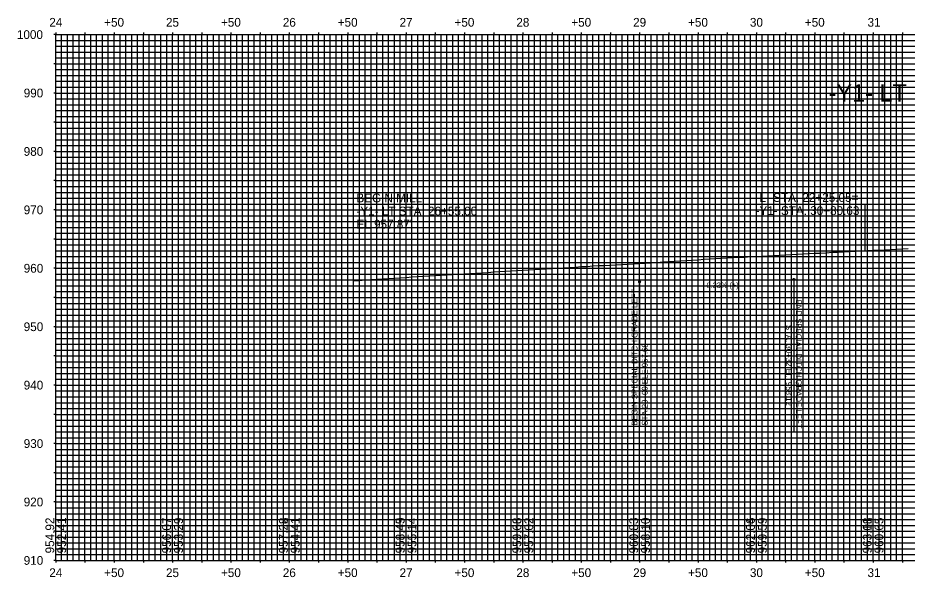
# Model space of a CAD drawing. Extents: x 1367 to 2832, y 896 to 1374.
# Drawn here: x 1367 to 2129, y 896 to 1374 of the extents above; entities that cross this region are included whole.
import ezdxf

# ---------------------------------------------------------------- set-up
doc = ezdxf.new("R2010")
doc.units = 0
for name, color, linetype in [('E_NCDOT_Terrain_Model_Contour_Major', 7, 'Continuous'), ('E_NCDOT_Vertical_Profile_Strip_Grade', 7, 'Continuous'), ('P_NCDOT_Horizontal_Alignment_Curve_and_Spiral_Data', 7, 'Continuous'), ('P_NCDOT_Horizontal_Alignment_Direction_Label', 7, 'Continuous'), ('P_NCDOT_Horizontal_Alignment_Station_Label', 7, 'Continuous'), ('P_NCDOT_Horizontal_Alignment_Station_Major_Label', 7, 'Continuous'), ('P_NCDOT_Horizontal_Alignment_Tick_Large', 7, 'Continuous'), ('P_NCDOT_Horizontal_Alignment_Tick_Small', 7, 'Continuous'), ('P_NCDOT_Vertical_Profile_Ditch_Grade_Left_Label', 7, 'Continuous'), ('P_NCDOT_Vertical_Profile_Ditch_Grade_Right', 7, 'Continuous'), ('P_NCDOT_Vertical_Profile_Strip_Grade', 7, 'Continuous'), ('P_RDY_Profile_Special_Ditch_L', 7, 'Continuous')]:
    doc.layers.add(name, color=color, linetype=linetype)

msp = doc.modelspace()

# ---------------------------------------------------------------- linework, layer by layer
at = {"layer": 'E_NCDOT_Terrain_Model_Contour_Major'}
msp.add_lwpolyline([(1655, 1149.35), (1660, 1149.68), (1665, 1150.01), (1670, 1150.35), (1675, 1150.68), (1680, 1151.01), (1685, 1151.32), (1690, 1151.61), (1695, 1151.94), (1700, 1152.23), (1705, 1152.56), (1710, 1152.88), (1715, 1153.19), (1720, 1153.46), (1725, 1153.76), (1730, 1154.05), (1735, 1154.35), (1740, 1154.67), (1745, 1154.97), (1750, 1155.27), (1755, 1155.59), (1760, 1155.91), (1765, 1156.22), (1770, 1156.51), (1775, 1156.83), (1780, 1157.13), (1785, 1157.44), (1790, 1157.76), (1795, 1158.07), (1800, 1158.38), (1805, 1158.69), (1810, 1159), (1815, 1159.32), (1820, 1159.61), (1825, 1159.91), (1830, 1160.22), (1835, 1160.49), (1840, 1160.79), (1845, 1161.09), (1850, 1161.39), (1855, 1161.67), (1860, 1161.98), (1865, 1162.25), (1870, 1162.53), (1875, 1162.81), (1880, 1163.07), (1885, 1163.34), (1890, 1163.56), (1895, 1163.85), (1900, 1164.14), (1905, 1164.46), (1910, 1164.77), (1915, 1165.09), (1920, 1165.44), (1925, 1165.75), (1930, 1166.06), (1935, 1166.37), (1940, 1166.68), (1945, 1167.01), (1950, 1167.34), (1955, 1167.67), (1960, 1167.99), (1965, 1168.32), (1970, 1168.64), (1975, 1168.91), (1980, 1169.16), (1985, 1169.41), (1990, 1169.66), (1995, 1169.96), (2000, 1170.22), (2005, 1170.5), (2010, 1170.77), (2015, 1171.06), (2020, 1171.32), (2025, 1171.59), (2030, 1171.87), (2035, 1172.1), (2040, 1172.36), (2045, 1172.59), (2050, 1172.83), (2055, 1173.08), (2060, 1173.36), (2065, 1173.66), (2070, 1173.88), (2075, 1174.15), (2080, 1174.41), (2085, 1174.68), (2090, 1174.94), (2095, 1175.17), (2100, 1175.4), (2105, 1175.63), (2110, 1175.86), (2115, 1176.11), (2120, 1176.36), (2125, 1176.6), (2130, 1176.87)], dxfattribs=at)
at = {"layer": 'P_NCDOT_Horizontal_Alignment_Station_Label'}
for p, q in [((1450, 910), (1450, 1360)), ((1500, 910), (1500, 1360)), ((1550, 910), (1550, 1360)), ((1600, 910), (1600, 1360)), ((1650, 910), (1650, 1360)), ((1700, 910), (1700, 1360)), ((1750, 910), (1750, 1360)), ((1800, 910), (1800, 1360)), ((1850, 910), (1850, 1360)), ((1900, 910), (1900, 1360)), ((1950, 910), (1950, 1360)), ((2000, 910), (2000, 1360)), ((2050, 910), (2050, 1360)), ((2100, 910), (2100, 1360)), ((1400, 1310), (2800, 1310)), ((1400, 1260), (2800, 1260)), ((1400, 1210), (2800, 1210)), ((1400, 1160), (2800, 1160)), ((1400, 1110), (2800, 1110)), ((1400, 1060), (2800, 1060)), ((1400, 1010), (2800, 1010)), ((1400, 960), (2800, 960))]:
    msp.add_line(p, q, dxfattribs=at)
at = {"layer": 'P_NCDOT_Horizontal_Alignment_Station_Major_Label'}
for p, q in [((1405, 910), (1405, 1360)), ((1410, 910), (1410, 1360)), ((1415, 910), (1415, 1360)), ((1420, 910), (1420, 1360)), ((1430, 910), (1430, 1360)), ((1435, 910), (1435, 1360)), ((1440, 910), (1440, 1360)), ((1445, 910), (1445, 1360)), ((1455, 910), (1455, 1360)), ((1460, 910), (1460, 1360)), ((1465, 910), (1465, 1360)), ((1470, 910), (1470, 1360)), ((1480, 910), (1480, 1360)), ((1485, 910), (1485, 1360)), ((1490, 910), (1490, 1360)), ((1495, 910), (1495, 1360)), ((1505, 910), (1505, 1360)), ((1510, 910), (1510, 1360)), ((1515, 910), (1515, 1360)), ((1520, 910), (1520, 1360)), ((1530, 910), (1530, 1360)), ((1535, 910), (1535, 1360)), ((1540, 910), (1540, 1360)), ((1545, 910), (1545, 1360)), ((1555, 910), (1555, 1360)), ((1560, 910), (1560, 1360)), ((1565, 910), (1565, 1360)), ((1570, 910), (1570, 1360)), ((1580, 910), (1580, 1360)), ((1585, 910), (1585, 1360)), ((1590, 910), (1590, 1360)), ((1595, 910), (1595, 1360)), ((1605, 910), (1605, 1360)), ((1610, 910), (1610, 1360)), ((1615, 910), (1615, 1360)), ((1620, 910), (1620, 1360)), ((1630, 910), (1630, 1360)), ((1635, 910), (1635, 1360)), ((1640, 910), (1640, 1360)), ((1645, 910), (1645, 1360)), ((1655, 910), (1655, 1360)), ((1660, 910), (1660, 1360)), ((1665, 910), (1665, 1360)), ((1670, 910), (1670, 1360)), ((1680, 910), (1680, 1360)), ((1685, 910), (1685, 1360)), ((1690, 910), (1690, 1360)), ((1695, 910), (1695, 1360)), ((1705, 910), (1705, 1360)), ((1710, 910), (1710, 1360)), ((1715, 910), (1715, 1360)), ((1720, 910), (1720, 1360)), ((1730, 910), (1730, 1360)), ((1735, 910), (1735, 1360)), ((1740, 910), (1740, 1360)), ((1745, 910), (1745, 1360)), ((1755, 910), (1755, 1360)), ((1760, 910), (1760, 1360)), ((1765, 910), (1765, 1360)), ((1770, 910), (1770, 1360)), ((1780, 910), (1780, 1360)), ((1785, 910), (1785, 1360)), ((1790, 910), (1790, 1360)), ((1795, 910), (1795, 1360)), ((1805, 910), (1805, 1360)), ((1810, 910), (1810, 1360)), ((1815, 910), (1815, 1360)), ((1820, 910), (1820, 1360)), ((1830, 910), (1830, 1360)), ((1835, 910), (1835, 1360)), ((1840, 910), (1840, 1360)), ((1845, 910), (1845, 1360)), ((1855, 910), (1855, 1360)), ((1860, 910), (1860, 1360)), ((1865, 910), (1865, 1360)), ((1870, 910), (1870, 1360)), ((1880, 910), (1880, 1360)), ((1885, 910), (1885, 1360)), ((1890, 910), (1890, 1360)), ((1895, 910), (1895, 1360)), ((1905, 910), (1905, 1360)), ((1910, 910), (1910, 1360)), ((1915, 910), (1915, 1360)), ((1920, 910), (1920, 1360)), ((1930, 910), (1930, 1360)), ((1935, 910), (1935, 1360)), ((1940, 910), (1940, 1360)), ((1945, 910), (1945, 1360)), ((1955, 910), (1955, 1360)), ((1960, 910), (1960, 1360)), ((1965, 910), (1965, 1360)), ((1970, 910), (1970, 1360)), ((1980, 910), (1980, 1360)), ((1985, 910), (1985, 1360)), ((1990, 910), (1990, 1360)), ((1995, 910), (1995, 1360)), ((2005, 910), (2005, 1360)), ((2010, 910), (2010, 1360)), ((2015, 910), (2015, 1360)), ((2020, 910), (2020, 1360)), ((2030, 910), (2030, 1360)), ((2035, 910), (2035, 1360)), ((2040, 910), (2040, 1360)), ((2045, 910), (2045, 1360)), ((2055, 910), (2055, 1360)), ((2060, 910), (2060, 1360)), ((2065, 910), (2065, 1360)), ((2070, 910), (2070, 1360)), ((2080, 910), (2080, 1360)), ((2085, 910), (2085, 1360)), ((2090, 910), (2090, 1360)), ((2095, 910), (2095, 1360)), ((2105, 910), (2105, 1360)), ((2110, 910), (2110, 1360)), ((2115, 910), (2115, 1360)), ((2120, 910), (2120, 1360)), ((1400, 1355), (2800, 1355)), ((1400, 1350), (2800, 1350)), ((1400, 1345), (2800, 1345)), ((1400, 1340), (2800, 1340)), ((1400, 1330), (2800, 1330)), ((1400, 1325), (2800, 1325)), ((1400, 1320), (2800, 1320)), ((1400, 1315), (2800, 1315)), ((1400, 1305), (2800, 1305)), ((1400, 1300), (2800, 1300)), ((1400, 1295), (2800, 1295)), ((1400, 1290), (2800, 1290)), ((1400, 1280), (2800, 1280)), ((1400, 1275), (2800, 1275)), ((1400, 1270), (2800, 1270)), ((1400, 1265), (2800, 1265)), ((1400, 1255), (2800, 1255)), ((1400, 1250), (2800, 1250)), ((1400, 1245), (2800, 1245)), ((1400, 1240), (2800, 1240)), ((1400, 1230), (2800, 1230)), ((1400, 1225), (2800, 1225)), ((1400, 1220), (2800, 1220)), ((1400, 1215), (2800, 1215)), ((1400, 1205), (2800, 1205)), ((1400, 1200), (2800, 1200)), ((1400, 1195), (2800, 1195)), ((1400, 1190), (2800, 1190)), ((1400, 1180), (2800, 1180)), ((1400, 1175), (2800, 1175)), ((1400, 1170), (2800, 1170)), ((1400, 1165), (2800, 1165)), ((1400, 1155), (2800, 1155)), ((1400, 1150), (2800, 1150)), ((1400, 1145), (2800, 1145)), ((1400, 1140), (2800, 1140)), ((1400, 1130), (2800, 1130)), ((1400, 1125), (2800, 1125)), ((1400, 1120), (2800, 1120)), ((1400, 1115), (2800, 1115)), ((1400, 1105), (2800, 1105)), ((1400, 1100), (2800, 1100)), ((1400, 1095), (2800, 1095)), ((1400, 1090), (2800, 1090)), ((1400, 1080), (2800, 1080)), ((1400, 1075), (2800, 1075)), ((1400, 1070), (2800, 1070)), ((1400, 1065), (2800, 1065)), ((1400, 1055), (2800, 1055)), ((1400, 1050), (2800, 1050)), ((1400, 1045), (2800, 1045)), ((1400, 1040), (2800, 1040)), ((1400, 1030), (2800, 1030)), ((1400, 1025), (2800, 1025)), ((1400, 1020), (2800, 1020)), ((1400, 1015), (2800, 1015)), ((1400, 1005), (2800, 1005)), ((1400, 1000), (2800, 1000)), ((1400, 995), (2800, 995)), ((1400, 990), (2800, 990)), ((1400, 980), (2800, 980)), ((1400, 975), (2800, 975)), ((1400, 970), (2800, 970)), ((1400, 965), (2800, 965)), ((1400, 955), (2800, 955)), ((1400, 950), (2800, 950)), ((1400, 945), (2800, 945)), ((1400, 940), (2800, 940)), ((1400, 930), (2800, 930)), ((1400, 925), (2800, 925)), ((1400, 920), (2800, 920)), ((1400, 915), (2800, 915))]:
    msp.add_line(p, q, dxfattribs=at)
at = {"layer": 'P_NCDOT_Horizontal_Alignment_Tick_Large'}
for p, q in [((1400, 1360), (1398.2, 1360)), ((1400, 1361.8), (1400, 1360)), ((1425, 1361.8), (1425, 1360)), ((1425, 910), (1425, 1360)), ((1450, 1361.8), (1450, 1360)), ((1450, 910), (1450, 1360)), ((1475, 1361.8), (1475, 1360)), ((1475, 910), (1475, 1360)), ((1500, 1361.8), (1500, 1360)), ((1500, 910), (1500, 1360)), ((1525, 1361.8), (1525, 1360)), ((1525, 910), (1525, 1360)), ((1550, 1361.8), (1550, 1360)), ((1550, 910), (1550, 1360)), ((1575, 1361.8), (1575, 1360)), ((1575, 910), (1575, 1360)), ((1600, 1361.8), (1600, 1360)), ((1600, 910), (1600, 1360)), ((1625, 1361.8), (1625, 1360)), ((1625, 910), (1625, 1360)), ((1650, 1361.8), (1650, 1360)), ((1650, 910), (1650, 1360)), ((1675, 1361.8), (1675, 1360)), ((1675, 910), (1675, 1360)), ((1700, 1361.8), (1700, 1360)), ((1700, 910), (1700, 1360)), ((1725, 1361.8), (1725, 1360)), ((1725, 910), (1725, 1360)), ((1750, 1361.8), (1750, 1360)), ((1750, 910), (1750, 1360)), ((1775, 1361.8), (1775, 1360)), ((1775, 910), (1775, 1360)), ((1800, 1361.8), (1800, 1360)), ((1800, 910), (1800, 1360)), ((1825, 1361.8), (1825, 1360)), ((1825, 910), (1825, 1360)), ((1850, 1361.8), (1850, 1360)), ((1850, 910), (1850, 1360)), ((1875, 1361.8), (1875, 1360)), ((1875, 910), (1875, 1360)), ((1900, 1361.8), (1900, 1360)), ((1900, 910), (1900, 1360)), ((1925, 1361.8), (1925, 1360)), ((1925, 910), (1925, 1360)), ((1950, 1361.8), (1950, 1360)), ((1950, 910), (1950, 1360)), ((1975, 1361.8), (1975, 1360)), ((1975, 910), (1975, 1360)), ((2000, 1361.8), (2000, 1360)), ((2000, 910), (2000, 1360)), ((2025, 1361.8), (2025, 1360)), ((2025, 910), (2025, 1360)), ((2050, 1361.8), (2050, 1360)), ((2050, 910), (2050, 1360)), ((2075, 1361.8), (2075, 1360)), ((2075, 910), (2075, 1360)), ((2100, 1361.8), (2100, 1360)), ((2100, 910), (2100, 1360)), ((2125, 1361.8), (2125, 1360)), ((2125, 910), (2125, 1360)), ((1400, 1335), (1398.2, 1335)), ((1400, 1335), (2800, 1335)), ((1400, 1310), (1398.2, 1310)), ((1400, 1310), (2800, 1310)), ((1400, 1285), (1398.2, 1285)), ((1400, 1285), (2800, 1285)), ((1400, 1260), (1398.2, 1260)), ((1400, 1260), (2800, 1260)), ((1400, 1235), (1398.2, 1235)), ((1400, 1235), (2800, 1235)), ((1400, 1210), (1398.2, 1210)), ((1400, 1210), (2800, 1210)), ((1400, 1185), (1398.2, 1185)), ((1400, 1185), (2800, 1185)), ((1400, 1160), (1398.2, 1160)), ((1400, 1160), (2800, 1160)), ((1400, 1135), (1398.2, 1135)), ((1400, 1135), (2800, 1135)), ((1400, 1110), (1398.2, 1110)), ((1400, 1110), (2800, 1110)), ((1400, 1085), (1398.2, 1085)), ((1400, 1085), (2800, 1085)), ((1400, 1060), (1398.2, 1060)), ((1400, 1060), (2800, 1060)), ((1400, 1035), (1398.2, 1035)), ((1400, 1035), (2800, 1035)), ((1400, 1010), (1398.2, 1010)), ((1400, 1010), (2800, 1010)), ((1400, 985), (1398.2, 985)), ((1400, 985), (2800, 985)), ((1400, 960), (1398.2, 960)), ((1400, 960), (2800, 960)), ((1400, 935), (1398.2, 935)), ((1400, 935), (2800, 935)), ((1400, 910), (1398.2, 910)), ((1400, 910), (1400, 908.2)), ((1425, 910), (1425, 908.2)), ((1450, 910), (1450, 908.2)), ((1475, 910), (1475, 908.2)), ((1500, 910), (1500, 908.2)), ((1525, 910), (1525, 908.2)), ((1550, 910), (1550, 908.2)), ((1575, 910), (1575, 908.2)), ((1600, 910), (1600, 908.2)), ((1625, 910), (1625, 908.2)), ((1650, 910), (1650, 908.2)), ((1675, 910), (1675, 908.2)), ((1700, 910), (1700, 908.2)), ((1725, 910), (1725, 908.2)), ((1750, 910), (1750, 908.2)), ((1775, 910), (1775, 908.2)), ((1800, 910), (1800, 908.2)), ((1825, 910), (1825, 908.2)), ((1850, 910), (1850, 908.2)), ((1875, 910), (1875, 908.2)), ((1900, 910), (1900, 908.2)), ((1925, 910), (1925, 908.2)), ((1950, 910), (1950, 908.2)), ((1975, 910), (1975, 908.2)), ((2000, 910), (2000, 908.2)), ((2025, 910), (2025, 908.2)), ((2050, 910), (2050, 908.2)), ((2075, 910), (2075, 908.2)), ((2100, 910), (2100, 908.2)), ((2125, 910), (2125, 908.2))]:
    msp.add_line(p, q, dxfattribs=at)
at = {"layer": 'P_NCDOT_Horizontal_Alignment_Tick_Small'}
for p, q in [((1400, 1360), (2800, 1360)), ((1400, 910), (1400, 1360)), ((1400, 910), (2800, 910))]:
    msp.add_line(p, q, dxfattribs=at)
at = {"layer": 'P_NCDOT_Vertical_Profile_Ditch_Grade_Left_Label'}
for p, q in [((2032, 1150.58), (2032, 1020)), ((1900, 1148.41), (1900, 1025.33))]:
    msp.add_line(p, q, dxfattribs=at)
for centre in [(2032, 1150.58), (1900, 1148.41)]:
    msp.add_circle(centre, 0.82, dxfattribs=at)
at = {"layer": 'P_NCDOT_Vertical_Profile_Ditch_Grade_Right'}
for p, q in [((1655, 1149.35), (1655, 1215)), ((1655, 1215), (1762.9, 1215)), ((1998.5, 1215), (2093.26, 1215)), ((2093.26, 1175.09), (2093.26, 1215))]:
    msp.add_line(p, q, dxfattribs=at)

# ---------------------------------------------------------------- texts
at = {"layer": 'E_NCDOT_Vertical_Profile_Strip_Grade'}
for s, p in [('952.41', (1408.83, 916)), ('953.29', (1508.85, 916)), ('954.41', (1608.85, 916)), ('955.14', (1708.81, 916)), ('957.02', (1808.85, 916)), ('958.10', (1908.81, 916)), ('959.59', (2008.82, 916)), ('960.65', (2108.71, 916))]:
    msp.add_text(s, height=7.5, rotation=90, dxfattribs=at).set_placement(p)
at = {"layer": 'P_NCDOT_Horizontal_Alignment_Curve_and_Spiral_Data'}
for s, p in [('24', (1394.43, 1366.75)), ('+50', (1441.46, 1366.75)), ('25', (1494.38, 1366.75)), ('+50', (1541.46, 1366.75)), ('26', (1594.41, 1366.75)), ('+50', (1641.46, 1366.75)), ('27', (1694.41, 1366.75)), ('+50', (1741.46, 1366.75)), ('28', (1794.41, 1366.75)), ('+50', (1841.46, 1366.75)), ('29', (1894.41, 1366.75)), ('+50', (1941.46, 1366.75)), ('30', (1994.43, 1366.75)), ('+50', (2041.46, 1366.75)), ('31', (2095.14, 1366.75)), ('24', (1394.43, 895.75)), ('+50', (1441.46, 895.75)), ('25', (1494.38, 895.75)), ('+50', (1541.46, 895.75)), ('26', (1594.41, 895.75)), ('+50', (1641.46, 895.75)), ('27', (1694.41, 895.75)), ('+50', (1741.46, 895.75)), ('28', (1794.41, 895.75)), ('+50', (1841.46, 895.75)), ('29', (1894.41, 895.75)), ('+50', (1941.46, 895.75)), ('30', (1994.43, 895.75)), ('+50', (2041.46, 895.75)), ('31', (2095.14, 895.75))]:
    msp.add_text(s, height=7.5, dxfattribs=at).set_placement(p)
at = {"layer": 'P_NCDOT_Horizontal_Alignment_Direction_Label'}
msp.add_text('-Y1- LT', height=15, dxfattribs=at).set_placement((2061.85, 1302.52))
at = {"layer": 'P_NCDOT_Vertical_Profile_Ditch_Grade_Left_Label'}
for s, height, rotation, p in [('0.33% (+)', 4.724, 0.36515, (1957.28, 1143.04)), ('BEGIN SPECIAL DITCH GRADE LEFT', 5, 90, (1898.13, 1025.33)), ('END SPECIAL DITCH GRADE LEFT ', 5, 270, (2033.76, 1133.26)), ('STA. 30+32 El.  958.12', 5, 270, (2025.26, 1111.57)), ('STA 29+00 ELE 957.68', 5, 90, (1906.88, 1025.33))]:
    msp.add_text(s, height=height, rotation=rotation, dxfattribs=at).set_placement(p)
at = {"layer": 'P_NCDOT_Vertical_Profile_Ditch_Grade_Right'}
for s, p in [('BEGIN MILL', (1657.48, 1216.47)), ('-L- STA. 22+25.05=', (1999.26, 1216.86)), ('-Y1- LT STA. 26+55.00', (1657.48, 1205.22)), ('-Y1- STA. 30+80.63', (1999.26, 1205.61)), ("EL 957.87'", (1657.48, 1193.97))]:
    msp.add_text(s, height=7.5, dxfattribs=at).set_placement(p)
at = {"layer": 'P_NCDOT_Vertical_Profile_Strip_Grade'}
for s, p in [('954.92', (1398.66, 916)), ('954.92', (1398.66, 916)), ('956.07', (1498.66, 916)), ('956.07', (1498.66, 916)), ('957.28', (1598.66, 916)), ('957.22', (1598.66, 916)), ('958.45', (1698.66, 916)), ('958.49', (1698.66, 916)), ('959.68', (1798.66, 916)), ('959.66', (1798.66, 916)), ('960.83', (1898.66, 916)), ('960.83', (1898.66, 916)), ('962.04', (1998.66, 916)), ('962.06', (1998.66, 916)), ('963.08', (2098.66, 916)), ('963.11', (2098.66, 916))]:
    msp.add_text(s, height=7.5, rotation=90, dxfattribs=at).set_placement(p)
at = {"layer": 'P_RDY_Profile_Special_Ditch_L'}
for s, p in [('1000', (1366.7, 1356.25)), ('990', (1372.53, 1306.25)), ('980', (1372.53, 1256.25)), ('970', (1372.53, 1206.25)), ('960', (1372.53, 1156.25)), ('950', (1372.53, 1106.25)), ('940', (1372.53, 1056.25)), ('930', (1372.53, 1006.25)), ('920', (1372.53, 956.25)), ('910', (1372.53, 906.25))]:
    msp.add_text(s, height=7.5, dxfattribs=at).set_placement(p)

doc.saveas('drawing.dxf')
